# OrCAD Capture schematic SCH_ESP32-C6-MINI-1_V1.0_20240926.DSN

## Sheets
1 01_DesignBlock: title: ESP32-C6-MINI-1; rev: V1.0; note: <01_DesignBlock>
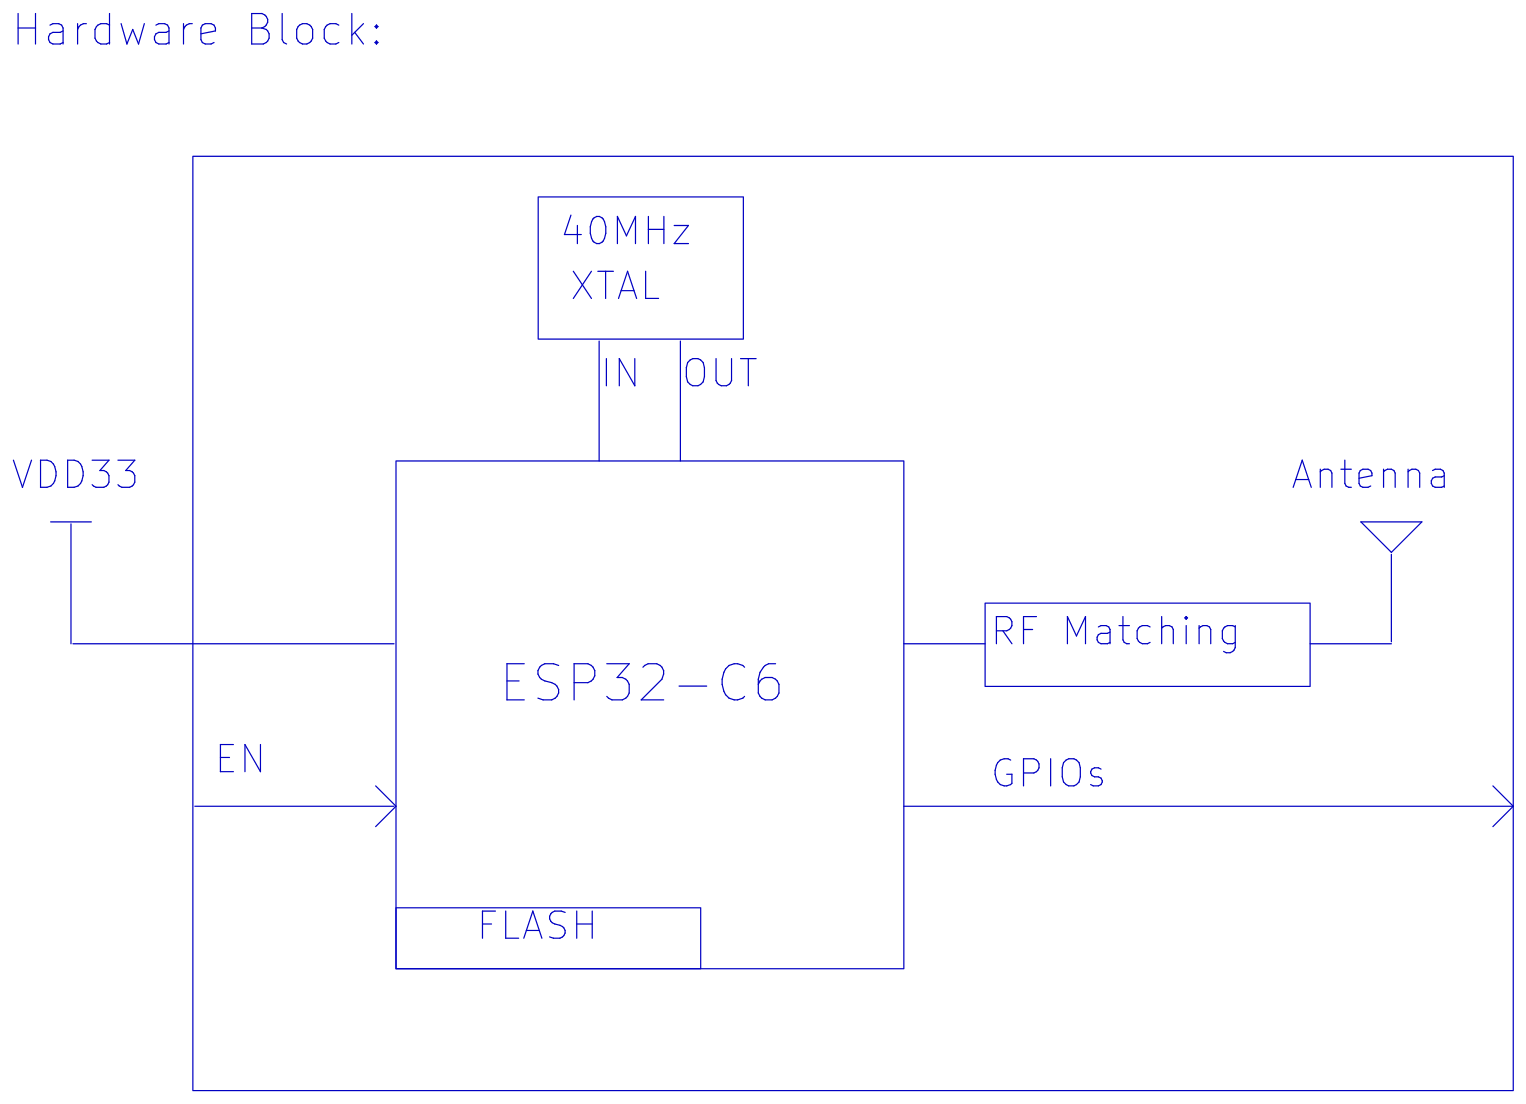
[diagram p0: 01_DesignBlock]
2 02_ESP32-C6-MINI-1: size A4; title: <ESP32-C6-MINI-1>; note: <02_ESP32-C6-MINI-1>
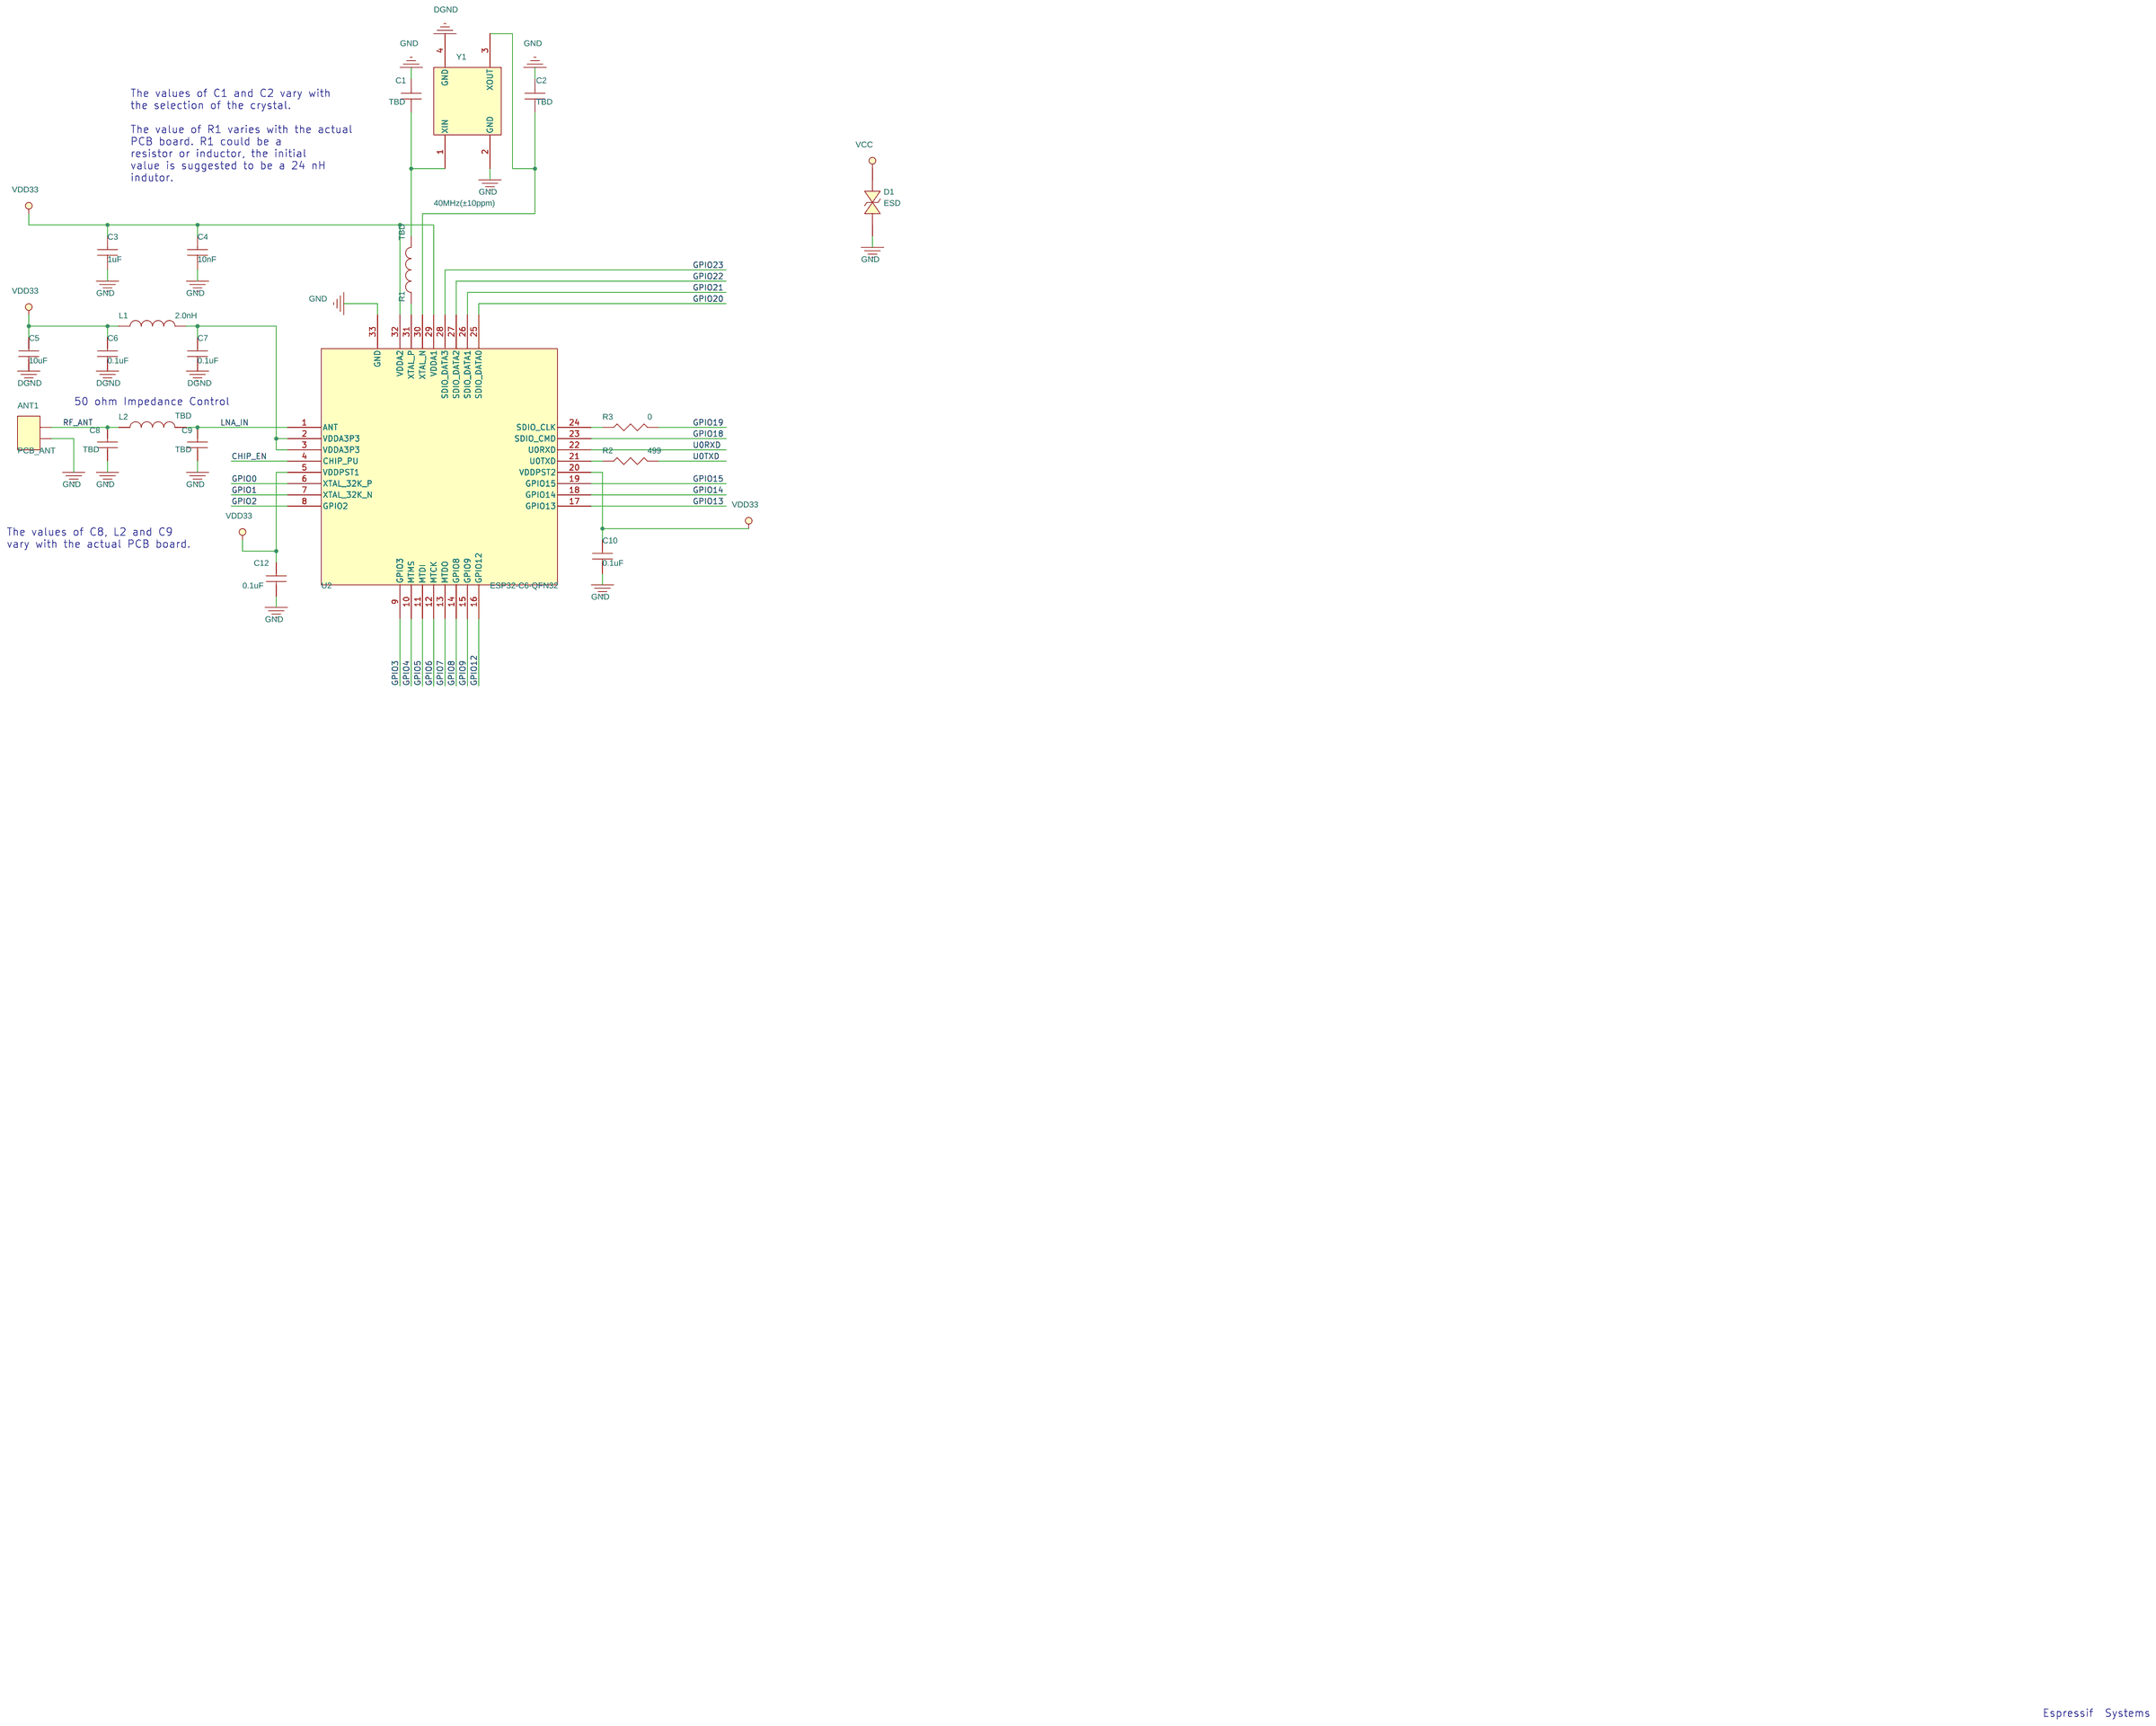
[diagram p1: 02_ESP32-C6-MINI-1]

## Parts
ANT1  PCB_ANT  [MINI-ANT-TYPED-H]
C1  TBD  [C0201]
C2  TBD  [C0201]
C3  1uF  [C0201]
C4  10nF  [C0201]
C5  10uF  [C0402]
C6  0.1uF  [C0201]
C7  0.1uF  [C0201]
C8  TBD  [C0201]
C9  TBD  [C0201]
C10  0.1uF  [C0201]
C12  0.1uF  [C0201]
D1  ESD  [SOD882]
L1  2.0nH  [L0201]
L2  TBD  [L0201]
R1  TBD  [R0201]
R2  499  [R0201]
R3  0  [R0201]
U2  ESP32-C6-QFN32  [QFN32_0P5_5_E3P7X3P2]
Y1  40MHz(±10ppm)  [XTAL3225]

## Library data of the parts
ANT1 = PCB_ANT
C1 C2 C8 C9 = CAP
C3 = CAPACITOR: CODE12: ES11.02.610.2.7.1.00; Part Number: ES11026102710000; Part Type: Capacitor
C4 = CAPACITOR: CODE12: ES11.02.410.2.6.2.00; Part Number: ES11024102620000; Part Type: Capacitor
C5 = CAPACITOR: CODE12: ES11.04.710.2.7.1.00; Part Number: ES11047102710000; Part Type: Capacitor
C6 C7 C10 C12 = CAPACITOR: CODE12: ES11.02.510.2.6.1.00; Part Number: ES11025102610001; Part Type: Capacitor
D1 = DIODE_BI_DIR: CODE12: ES31.32.0010.00.0.0; Part Number: ES31320010000001; Part Type: Diode
L1 = INDUCTOR: CODE12: ES31.02.020.1.AA.0.0; Part Number: ES31020201AA0001; Part Type: Inductor
L2 = Inductor
R1 = INDUCTOR
R2 = RESISTOR: CODE12: ES21.02.2499.1.00.0; Part Number: ES21022499100000; Part Type: Resistor
R3 = RESISTOR: CODE12: ES21.02.0000.1.00.0; Part Number: ES21020000100000; Part Type: Resistor
U2 = ESP32-C6-QFN32
Y1 = XTAL_4P: CODE12: ES31.50.4400.1.A.1.0; Part Number: ES315044001A1000; Part Type: Clock

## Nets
GND: ANT1.2 C1.2 C2.2 C3.2 C4.2 C5.2 C6.2 C7.2 C8.1 C9.1 C10.2 C12.2 D1.2 U2.33(GND) Y1.2(GND) Y1.4(GND)
VDD33: C3.1 C4.1 C5.1 C6.1 C10.1 C12.1 D1.1 L1.1 U2.5(VDDPST1) U2.20(VDDPST2) U2.29(VDDA1) U2.32(VDDA2)
CHIP_EN: U2.4(CHIP_PU)
GPIO0: U2.6(XTAL_32K_P)
GPIO1: U2.7(XTAL_32K_N)
GPIO2: U2.8(GPIO2)
GPIO3: U2.9(GPIO3)
GPIO4: U2.10(MTMS)
GPIO5: U2.11(MTDI)
GPIO6: U2.12(MTCK)
GPIO7: U2.13(MTDO)
GPIO8: U2.14(GPIO8)
GPIO9: U2.15(GPIO9)
GPIO12: U2.16(GPIO12)
GPIO13: U2.17(GPIO13)
GPIO14: U2.18(GPIO14)
GPIO15: U2.19(GPIO15)
GPIO18: U2.23(SDIO_CMD)
GPIO19: R3.2
GPIO20: U2.25(SDIO_DATA0)
GPIO21: U2.26(SDIO_DATA1)
GPIO22: U2.27(SDIO_DATA2)
GPIO23: U2.28(SDIO_DATA3)
LNA_IN: C9.2 L2.1 U2.1(ANT)
RF_ANT: ANT1.1 C8.2 L2.2
U0RXD: U2.22(U0RXD)
U0TXD: R2.2
N16985797: C2.1 U2.30(XTAL_N) Y1.3(XOUT)
N16985859: C7.1 L1.2 U2.2(VDDA3P3) U2.3(VDDA3P3)
N16985998: R2.1 U2.21(U0TXD)
N16986010: R3.1 U2.24(SDIO_CLK)
N16986051: R1.2 U2.31(XTAL_P)
N16986053: C1.1 R1.1 Y1.1(XIN)

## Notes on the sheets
sheet 1
- Hardware Block:
- 40MHz
- XTAL
- IN
- OUT
- VDD33
- Antenna
- RF Matching
- ESP32-C6
- EN
- GPIOs
- FLASH
sheet 2
- The values of C1 and C2 vary with
  the selection of the crystal.
  The value of R1 varies with the actual
  PCB board. R1 could be a
  resistor or inductor, the initial
  value is suggested to be a 24 nH
  indutor.
- 50 ohm Impedance Control
- The values of C8, L2 and C9
  vary with the actual PCB board.
- Espressif  Systems
